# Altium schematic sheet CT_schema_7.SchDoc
size 371 x 245 mm
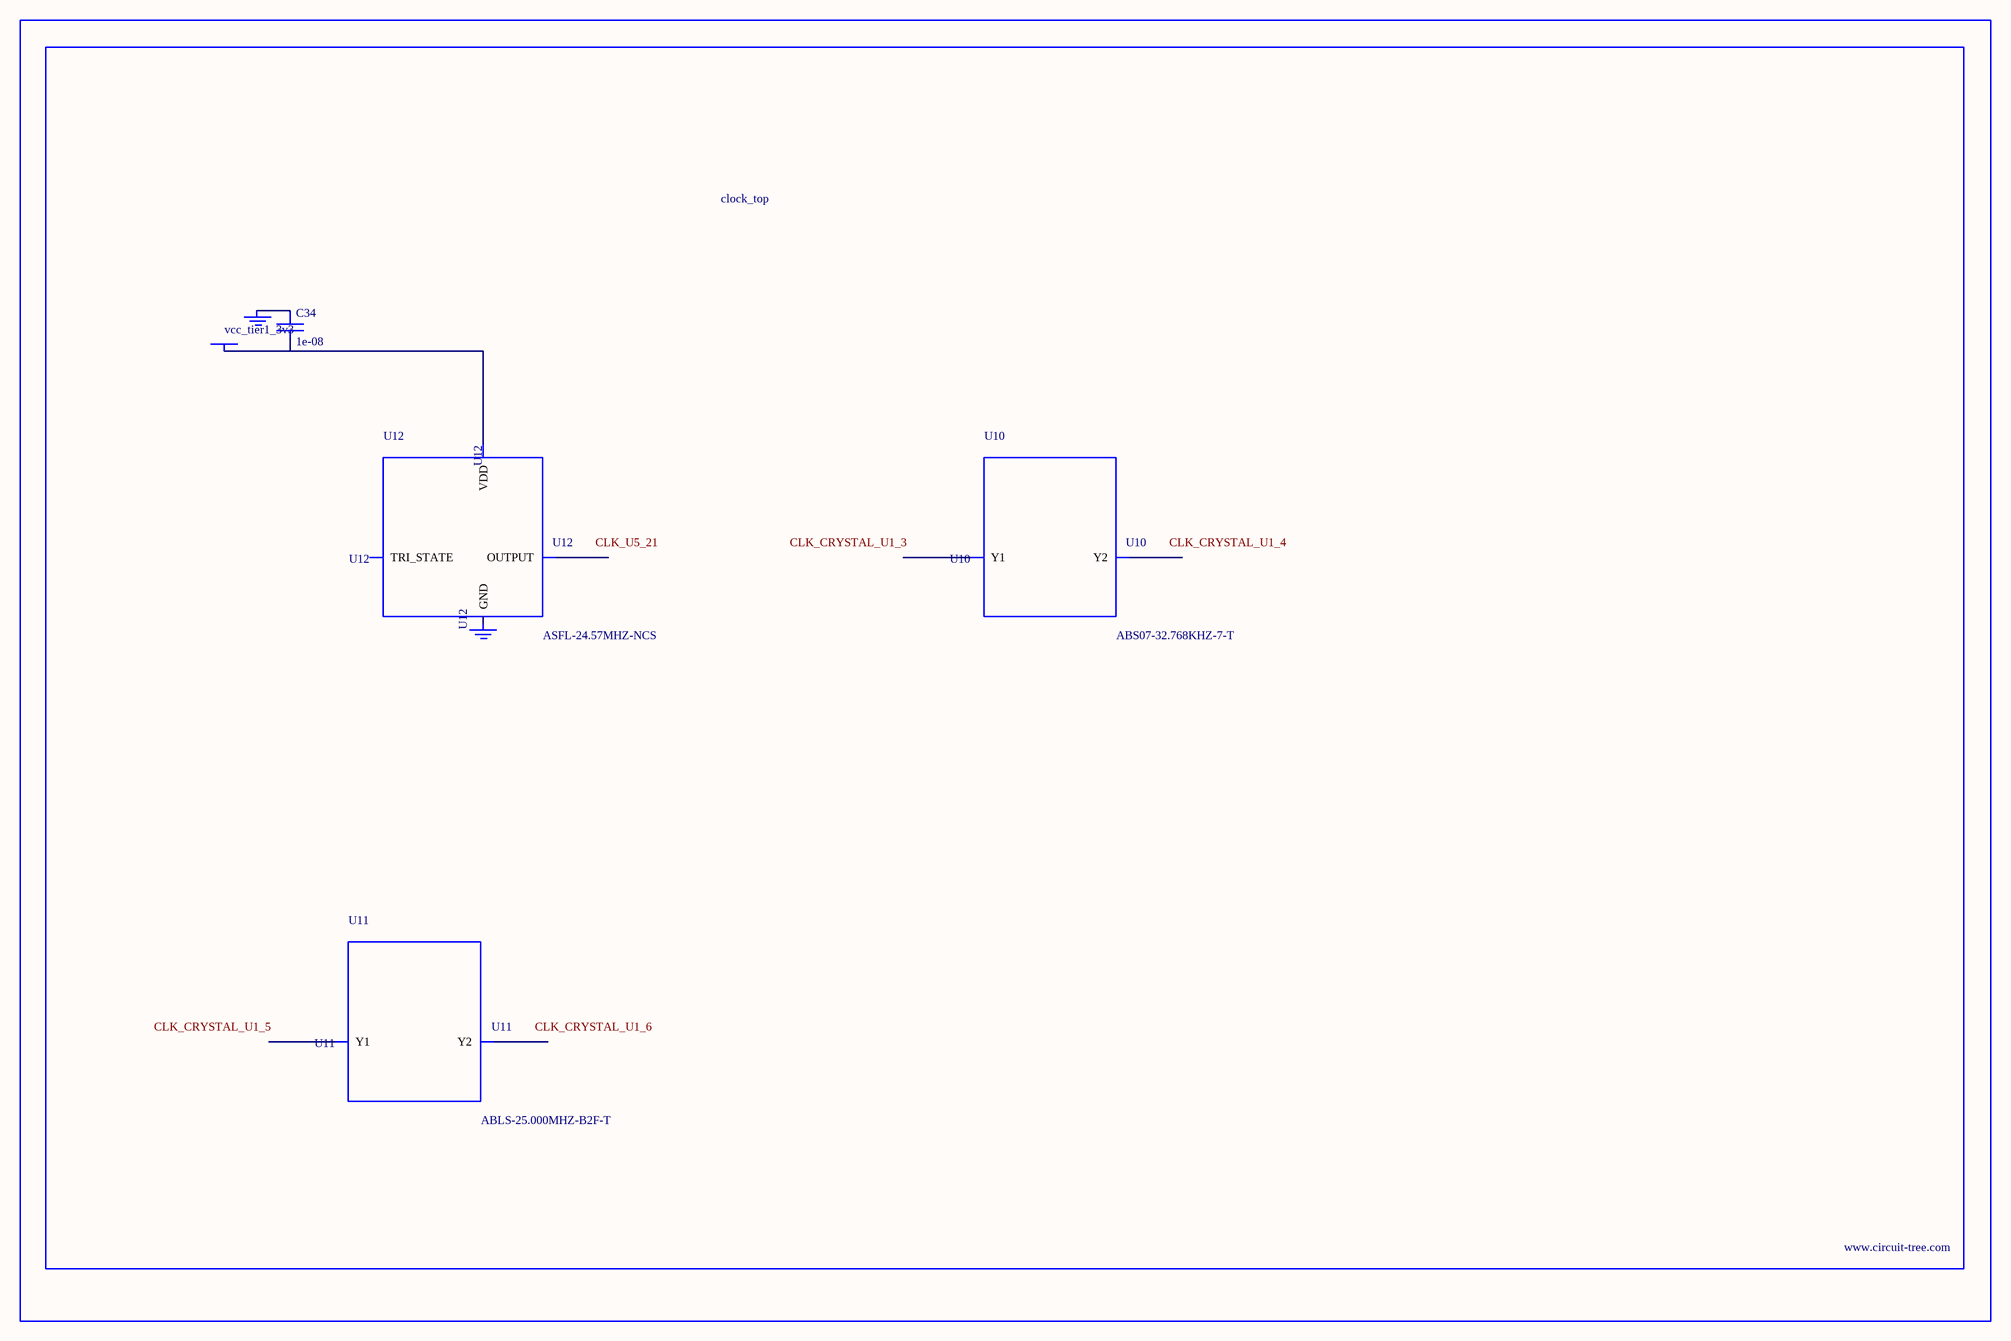
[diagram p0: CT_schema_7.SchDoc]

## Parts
BORDER6  (no value)
C34  1e-08  [C0402]
GND_INSTANCE_6_0  (no value)
GND_INSTANCE_6_1  (no value)
POWER_INSTANCE_6_0  vcc_tier1_3v3
U10  ABS07-32.768KHZ-7-T  [ABS07-32.768KHZ-7-T]
U11  ABLS-25.000MHZ-B2F-T  [ABLS-25.000MHZ-B2F-T]
U12  ASFL-24.57MHZ-NCS  [ASFL1]

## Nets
NetC34_1: C34.1 GND_INSTANCE_6_0.0(GND)
NetC34_2: C34.2 POWER_INSTANCE_6_0.0(PWR) U12.4(VDD)

Not connected (* = marked no-connect by the designer): GND_INSTANCE_6_1 0(GND); U10 1(Y1) 2(Y2); U11 1(Y1) 2(Y2); U12 1(TRI_STATE) 2(GND) 3(OUTPUT)

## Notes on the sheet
- Labels drawn without touching a wire or pin: CLK_CRYSTAL_U1_3, CLK_CRYSTAL_U1_4, CLK_CRYSTAL_U1_5, CLK_CRYSTAL_U1_6, CLK_U5_21

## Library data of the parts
BORDER6 = BORDER_PAGE6
C34 = C0402C103K3RAC
GND_INSTANCE_6_0 GND_INSTANCE_6_1 = GND
POWER_INSTANCE_6_0 = PWR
